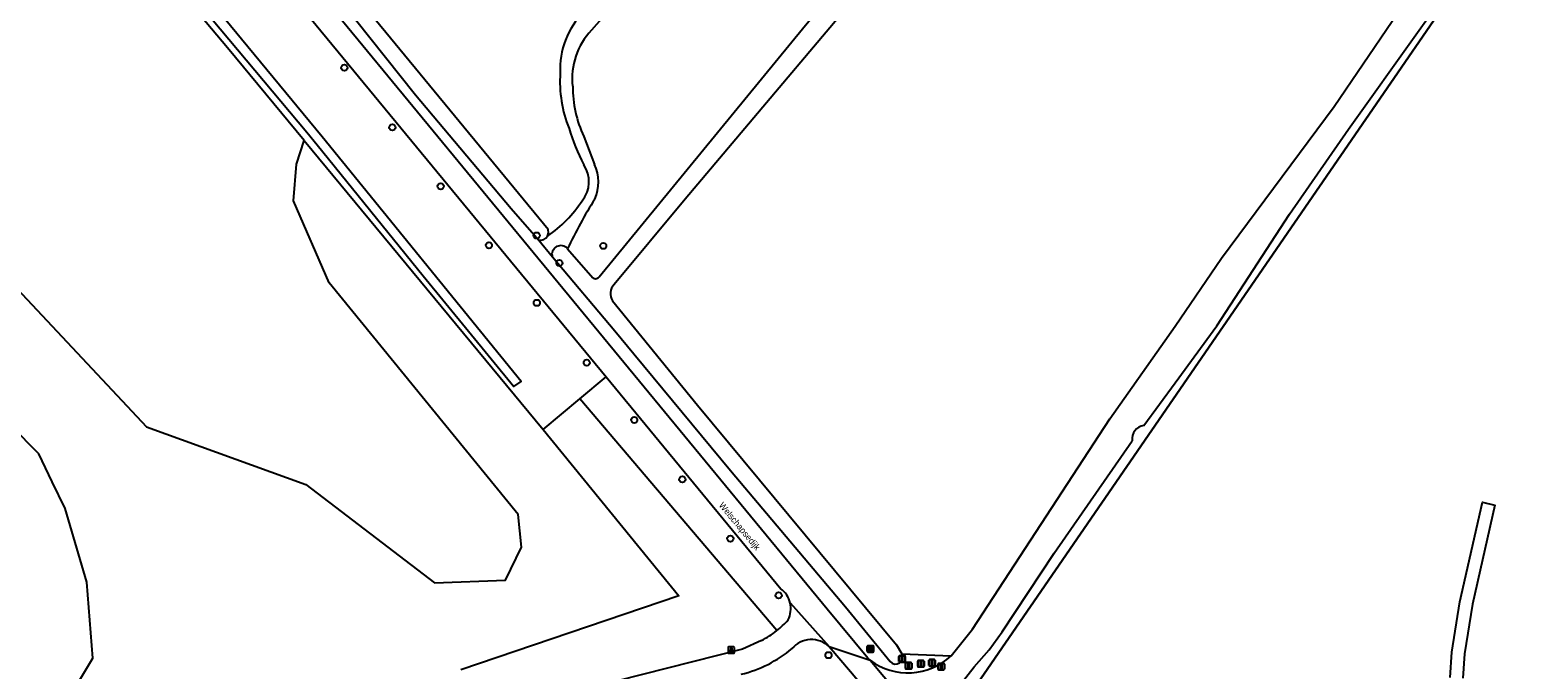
# Model space of a CAD drawing. Extents: x 156061 to 157804, y 383451 to 385640.
# Drawn here: x 156819.9 to 157057.1, y 384634.6 to 384735.1 of the extents above; entities that cross this region are included whole.
import ezdxf

# ---------------------------------------------------------------- set-up
doc = ezdxf.new("R2010")
doc.units = 0
for name, color, linetype in [('IMGEO_Afsluitpaal', 7, 'Continuous'), ('IMGEO_Berm_groen', 7, 'Continuous'), ('IMGEO_Boom', 7, 'Continuous'), ('IMGEO_Fietspad_gesloten', 7, 'Continuous'), ('IMGEO_Gemengd_bos', 7, 'Continuous'), ('IMGEO_Grasland_overig', 7, 'Continuous'), ('IMGEO_Groenvoorziening', 7, 'Continuous'), ('IMGEO_Hek', 7, 'Continuous'), ('IMGEO_Lichtpunt', 7, 'Continuous'), ('IMGEO_Loofbos', 7, 'Continuous'), ('IMGEO_Openbare_ruimte_label', 7, 'Continuous'), ('IMGEO_Waterloop', 7, 'Continuous'), ('IMGEO_Wegwijzer', 7, 'Continuous')]:
    doc.layers.add(name, color=color, linetype=linetype)

msp = doc.modelspace()

# ---------------------------------------------------------------- linework, layer by layer
at = {"layer": 'IMGEO_Afsluitpaal'}
for p, q in [((156956.65, 384636.8), (156957.44, 384636.8)), ((156957.44, 384636.8), (156956.65, 384636.8)), ((156956.55, 384635.9), (156956.55, 384636.7)), ((156956.55, 384636.7), (156956.55, 384635.9)), ((156957.44, 384635.8), (156956.65, 384635.8)), ((156956.65, 384635.8), (156957.44, 384635.8)), ((156957.54, 384636.7), (156957.54, 384635.9)), ((156957.54, 384635.9), (156957.54, 384636.7)), ((156957.57, 384634.84), (156957.57, 384635.64)), ((156957.57, 384635.64), (156957.57, 384634.84)), ((156957.67, 384635.74), (156958.46, 384635.74)), ((156958.46, 384635.74), (156957.67, 384635.74)), ((156958.46, 384634.74), (156957.67, 384634.74)), ((156957.67, 384634.74), (156958.46, 384634.74)), ((156958.56, 384635.64), (156958.56, 384634.84)), ((156958.56, 384634.84), (156958.56, 384635.64)), ((156959.52, 384635.15), (156959.52, 384635.95)), ((156959.52, 384635.95), (156959.52, 384635.15)), ((156959.62, 384636.05), (156960.41, 384636.05)), ((156960.41, 384636.05), (156959.62, 384636.05)), ((156960.41, 384635.05), (156959.62, 384635.05)), ((156959.62, 384635.05), (156960.41, 384635.05)), ((156960.51, 384635.95), (156960.51, 384635.15)), ((156960.51, 384635.15), (156960.51, 384635.95)), ((156961.26, 384635.29), (156961.26, 384636.09)), ((156961.26, 384636.09), (156961.26, 384635.29)), ((156961.36, 384636.19), (156962.15, 384636.19)), ((156962.15, 384636.19), (156961.36, 384636.19)), ((156962.15, 384635.19), (156961.36, 384635.19)), ((156961.36, 384635.19), (156962.15, 384635.19)), ((156962.25, 384636.09), (156962.25, 384635.29)), ((156962.25, 384635.29), (156962.25, 384636.09)), ((156962.72, 384634.71), (156962.72, 384635.5)), ((156962.72, 384635.5), (156962.72, 384634.71)), ((156962.82, 384635.6), (156963.61, 384635.6)), ((156963.61, 384635.6), (156962.82, 384635.6)), ((156963.61, 384634.61), (156962.82, 384634.61)), ((156962.82, 384634.61), (156963.61, 384634.61)), ((156963.71, 384635.5), (156963.71, 384634.71)), ((156963.71, 384634.71), (156963.71, 384635.5))]:
    msp.add_line(p, q, dxfattribs=at)
for points in [[(156956.97, 384636.67), (156957.12, 384636.67), (156957.12, 384635.92), (156956.97, 384635.92), (156956.97, 384636.67)], [(156957.99, 384635.62), (156958.14, 384635.62), (156958.14, 384634.87), (156957.99, 384634.87), (156957.99, 384635.62)], [(156959.94, 384635.92), (156960.09, 384635.92), (156960.09, 384635.17), (156959.94, 384635.17), (156959.94, 384635.92)], [(156961.68, 384636.07), (156961.83, 384636.07), (156961.83, 384635.32), (156961.68, 384635.32), (156961.68, 384636.07)], [(156963.14, 384635.48), (156963.29, 384635.48), (156963.29, 384634.73), (156963.14, 384634.73), (156963.14, 384635.48)]]:
    msp.add_lwpolyline(points, dxfattribs=at)
for centre, start, end in [((156956.65, 384636.7), 90, 180), ((156956.65, 384636.7), 90, 180), ((156957.44, 384636.7), 0, 90), ((156957.44, 384636.7), 360, 90), ((156956.65, 384635.9), 180, 270), ((156956.65, 384635.9), 180, 270), ((156957.44, 384635.9), 270, 0), ((156957.44, 384635.9), 270, 0), ((156957.67, 384635.64), 90, 180), ((156957.67, 384635.64), 90, 180), ((156957.67, 384634.84), 180, 270), ((156957.67, 384634.84), 180, 270), ((156958.46, 384635.64), 0, 90), ((156958.46, 384635.64), 360, 90), ((156958.46, 384634.84), 270, 0), ((156958.46, 384634.84), 270, 0), ((156959.62, 384635.95), 90, 180), ((156959.62, 384635.95), 90, 180), ((156959.62, 384635.15), 180, 270), ((156959.62, 384635.15), 180, 270), ((156960.41, 384635.95), 0, 90), ((156960.41, 384635.95), 360, 90), ((156960.41, 384635.15), 270, 0), ((156960.41, 384635.15), 270, 0), ((156961.36, 384636.09), 90, 180), ((156961.36, 384636.09), 90, 180), ((156961.36, 384635.29), 180, 270), ((156961.36, 384635.29), 180, 270), ((156962.15, 384636.09), 0, 90), ((156962.15, 384636.09), 360, 90), ((156962.15, 384635.29), 270, 0), ((156962.15, 384635.29), 270, 0), ((156962.82, 384635.5), 90, 180), ((156962.82, 384635.5), 90, 180), ((156962.82, 384634.71), 180, 270), ((156962.82, 384634.71), 180, 270), ((156963.61, 384635.5), 0, 90), ((156963.61, 384635.5), 360, 90), ((156963.61, 384634.71), 270, 0), ((156963.61, 384634.71), 270, 0)]:
    msp.add_arc(centre, 0.1, start, end, dxfattribs=at)
at = {"layer": 'IMGEO_Berm_groen'}
for points in [[(156899.9, 384702.15), (156902.04, 384699.49)], [(156906.38, 384677.17), (156910.52, 384680.62)], [(156937.33, 384640.75), (156906.38, 384677.17)], [(156956.99, 384637.11), (156964.76, 384636.78)]]:
    msp.add_lwpolyline(points, dxfattribs=at)
msp.add_arc((156957.98, 384644.09), 9.97, 233.2442, 312.8511, dxfattribs=at)
at = {"layer": 'IMGEO_Boom'}
for centre in [(156869.33, 384729.23), (156876.89, 384719.86), (156884.49, 384710.59), (156899.59, 384702.86), (156892.06, 384701.33), (156910.04, 384701.23), (156903.16, 384698.52), (156899.6, 384692.28), (156907.46, 384682.86), (156914.92, 384673.86), (156922.49, 384664.52), (156930.05, 384655.21), (156937.63, 384646.3), (156945.48, 384636.9)]:
    msp.add_circle(centre, 0.489, dxfattribs=at)
at = {"layer": 'IMGEO_Fietspad_gesloten'}
for points in [[(156952.01, 384636.1), (156951.65, 384636.45), (156945.25, 384644.12), (156913.26, 384682.92), (156857.95, 384750), (156766.23, 384861.24), (156717.24, 384920.7), (156651.9, 385000), (156634.53, 385021.05), (156628.66, 385028.19), (156628.31, 385028.6), (156616.13, 385043.37), (156611.41, 385049.1), (156600.26, 385062.64)], [(156605.09, 385050.03), (156608.82, 385046.51), (156609.37, 385045.98), (156609.93, 385045.44), (156647.34, 385000), (156714.45, 384918.5), (156763.61, 384858.81), (156853.32, 384750), (156910.52, 384680.62)], [(156910.52, 384680.62), (156937.97, 384647.33)], [(156939.44, 384645.1), (156945.58, 384638.24)], [(156934.94, 384639.2), (156931.97, 384637.82), (156888.89, 384626.92)], [(156945.58, 384638.24), (156952.01, 384636.1)], [(156945.58, 384638.24), (156948.92, 384634.34), (156956.8, 384625), (156966.54, 384613.57), (156977.24, 384601.18), (156992.9, 384582.99), (157000, 384574.89), (157056.89, 384509.94)], [(156952.01, 384636.1), (156960.39, 384626.17), (156971.95, 384612.68), (156983.28, 384599.59)]]:
    msp.add_lwpolyline(points, dxfattribs=at)
for centre, radius, start, end in [((156935.65, 384644.19), 3.9, 13.3731, 53.5565), ((156935.66, 384644.2), 3.89, 333.0449, 13.3681), ((156928.05, 384652.4), 14.9, 308.5495, 318.0269), ((156928.18, 384652.24), 14.69, 297.4079, 308.5455), ((156942.8, 384635.34), 4.01, 46.2254, 139.9072), ((156927.2, 384652.9), 19.53, 283.3871, 309.9373)]:
    msp.add_arc(centre, radius, start, end, dxfattribs=at)
at = {"layer": 'IMGEO_Gemengd_bos'}
for points in [[(156912.63, 384740.14), (156908.19, 384735.13)], [(156812.3, 384700.37), (156835.91, 384675.25), (156838.21, 384672.8), (156863.25, 384663.73), (156883.49, 384648.27), (156894.67, 384648.67), (156897.2, 384653.87), (156896.68, 384658.99), (156866.93, 384695.43), (156861.35, 384708.33), (156861.8, 384714.05), (156863, 384717.8)], [(156863, 384717.8), (156900.59, 384672.36)], [(156906.98, 384718.4), (156908.69, 384714.03)], [(156821.01, 384621.8), (156829.78, 384636.4), (156828.83, 384648.36), (156825.41, 384659.94), (156823.39, 384664.13), (156821.27, 384668.56), (156808.2, 384681.7)]]:
    msp.add_lwpolyline(points, dxfattribs=at)
for centre, radius, start, end in [((156916.17, 384727.55), 11.01, 136.4739, 186.3634), ((156923.86, 384726.27), 18.62, 179.8157, 205.0017), ((156902.85, 384711.28), 6.45, 335.3938, 25.1966), ((156970.38, 384669.75), 72.88, 147.7934, 154.8019)]:
    msp.add_arc(centre, radius, start, end, dxfattribs=at)
at = {"layer": 'IMGEO_Grasland_overig'}
for points in [[(156995.06, 384673.02), (157000, 384679.72), (157006.58, 384688.65), (157018, 384706.19), (157027.27, 384719.55), (157049, 384750), (157049.73, 384751.02), (157051.71, 384756.32), (157067.45, 384779.73), (157078.82, 384797.04), (157111.19, 384845.3), (157125.06, 384865.65), (157130.13, 384872.27), (157130.21, 384872.37), (157130.3, 384872.46), (157130.39, 384872.55)], [(156964.76, 384636.78), (156968.13, 384640.98), (156989.71, 384674.03), (157000, 384688.61), (157007.27, 384699.31), (157025, 384723.12), (157043.24, 384750), (157047.44, 384756.19)], [(156964.63, 384630.23), (156968.41, 384635.04), (156970.77, 384637.72), (156972.78, 384640.58), (156980.96, 384652.91), (156993.25, 384670.61)], [(157043.26, 384633.37), (157043.53, 384637.35), (157044.79, 384645.29), (157048.34, 384660.93), (157050.29, 384660.49), (157046.76, 384644.91), (157045.52, 384637.12), (157045.25, 384633.28)]]:
    msp.add_lwpolyline(points, dxfattribs=at)
msp.add_arc((156995.39, 384670.88), 2.16, 98.7591, 187.3492, dxfattribs=at)
at = {"layer": 'IMGEO_Groenvoorziening'}
for points in [[(156863, 384717.8), (156850.94, 384732.38), (156844.21, 384740.36), (156836.09, 384750), (156826.08, 384762.21), (156800.19, 384793.8), (156738.88, 384868.16), (156719.79, 384891.58), (156704.18, 384910.35)], [(157158.87, 384852.91), (157148.97, 384858.97), (157139.5, 384863.28), (157133.04, 384863.79), (157129.5, 384863.26), (157126.71, 384861.14), (157124.21, 384858.2), (157109.09, 384836.1), (156966.05, 384628.27), (156979.27, 384612.75)]]:
    msp.add_lwpolyline(points, dxfattribs=at)
at = {"layer": 'IMGEO_Hek'}
msp.add_lwpolyline([(156979.27, 384612.75), (156966.05, 384628.27), (157109.09, 384836.1)], dxfattribs=at)
at = {"layer": 'IMGEO_Lichtpunt'}
for p, q in [((156929.69, 384638.1), (156929.69, 384637.29)), ((156929.69, 384638.1), (156929.69, 384637.29)), ((156930.59, 384638.2), (156929.78, 384638.2)), ((156930.59, 384638.2), (156929.78, 384638.2)), ((156929.78, 384637.2), (156930.59, 384637.2)), ((156929.78, 384637.2), (156930.59, 384637.2)), ((156930.68, 384637.29), (156930.68, 384638.1)), ((156930.68, 384637.29), (156930.68, 384638.1))]:
    msp.add_line(p, q, dxfattribs=at)
for points in [[(156930.06, 384637.76), (156930.1, 384637.74), (156929.91, 384637.47), (156929.87, 384637.5), (156930.06, 384637.76)], [(156930.16, 384637.72), (156930.21, 384637.72), (156930.21, 384637.39), (156930.16, 384637.39), (156930.16, 384637.72)], [(156930.27, 384637.74), (156930.31, 384637.76), (156930.5, 384637.5), (156930.46, 384637.47), (156930.27, 384637.74)]]:
    msp.add_lwpolyline(points, dxfattribs=at)
msp.add_circle((156930.19, 384637.9), 0.0994, dxfattribs=at)
for centre, start, end in [((156929.78, 384638.1), 90, 180), ((156929.78, 384638.1), 90, 180), ((156929.78, 384637.29), 180, 270), ((156929.78, 384637.29), 180, 270), ((156930.59, 384638.1), 0, 90), ((156930.59, 384638.1), 0, 90), ((156930.59, 384637.29), 270, 0), ((156930.59, 384637.29), 270, 360)]:
    msp.add_arc(centre, 0.0946, start, end, dxfattribs=at)
at = {"layer": 'IMGEO_Loofbos'}
for points in [[(156900.59, 384672.36), (156906.38, 384677.17)], [(156900.59, 384672.36), (156921.96, 384646.24), (156887.64, 384634.58)]]:
    msp.add_lwpolyline(points, dxfattribs=at)
for centre, radius, start, end in [((156916.16, 384728.98), 12.89, 135.5682, 182.6039), ((156923.09, 384727.06), 19.85, 176.1201, 201.885), ((156939.03, 384730.36), 35.99, 197.295, 207.0582), ((156903.1, 384711.32), 4.71, 320.4606, 34.4427), ((156889.74, 384719.54), 20.36, 304.5519, 326.5832)]:
    msp.add_arc(centre, radius, start, end, dxfattribs=at)
at = {"layer": 'IMGEO_Waterloop'}
for points in [[(156901.29, 384702.77), (156901.45, 384703.28), (156901.39, 384703.81), (156863.3, 384750), (156839.16, 384779.55), (156830.46, 384789.83)], [(156828.52, 384788.04), (156840.15, 384774.25), (156860.19, 384750), (156871.1, 384736.8), (156880.52, 384724.99), (156895.57, 384707.11), (156899.9, 384702.15)], [(156909.41, 384696.38), (156941.87, 384735.94), (156953.6, 384750), (156967.04, 384766.13), (156980.7, 384781.58)], [(156982.6, 384779.99), (156976.6, 384772.41), (156957.89, 384750), (156922.91, 384708.59), (156911.79, 384695.16)], [(156837.41, 384750.16), (156837.54, 384750), (156863.41, 384719.1), (156865.07, 384717.11), (156881.71, 384696.52), (156896, 384679.11), (156897.15, 384679.89), (156865.85, 384718.39), (156839.75, 384750), (156838.72, 384751.26), (156838.16, 384750.79), (156837.41, 384750.16)], [(156904.43, 384700.78), (156908.42, 384696.19)], [(156902.04, 384699.49), (156911.88, 384687.9), (156914.88, 384684.27), (156930.08, 384665.91), (156948.15, 384644.48), (156955.17, 384635.88)], [(156911.52, 384692.57), (156924.85, 384676.2), (156956.19, 384638.52), (156956.99, 384637.11)]]:
    msp.add_lwpolyline(points, dxfattribs=at)
for centre, radius, start, end in [((156900.17, 384703.41), 1.29, 257.867, 330.2723), ((156903.37, 384699.88), 1.39, 40.2824, 196.1053), ((156908.82, 384696.78), 0.709, 235.7789, 326.0137), ((156913.17, 384693.71), 2.01, 133.6096, 214.5842), ((156956.01, 384636.6), 1.11, 220.6341, 27.2814)]:
    msp.add_arc(centre, radius, start, end, dxfattribs=at)
at = {"layer": 'IMGEO_Wegwijzer'}
for p, q in [((156951.58, 384637.48), (156951.58, 384638.28)), ((156951.58, 384638.28), (156951.58, 384637.48)), ((156951.68, 384638.38), (156952.47, 384638.38)), ((156952.47, 384638.38), (156951.68, 384638.38)), ((156952.47, 384637.38), (156951.68, 384637.38)), ((156951.68, 384637.38), (156952.47, 384637.38)), ((156952.57, 384638.28), (156952.57, 384637.48)), ((156952.57, 384637.48), (156952.57, 384638.28))]:
    msp.add_line(p, q, dxfattribs=at)
for points in [[(156951.68, 384638.12), (156952.47, 384638.12), (156952.47, 384637.65), (156951.68, 384637.65), (156951.68, 384638.12)], [(156951.75, 384637.97), (156951.75, 384637.88), (156951.75, 384637.8), (156952.16, 384637.8), (156952.16, 384637.72), (156952.4, 384637.88), (156952.16, 384638.05), (156952.16, 384637.97), (156951.75, 384637.97)]]:
    msp.add_lwpolyline(points, dxfattribs=at)
for centre, start, end in [((156951.68, 384638.28), 90, 180), ((156951.68, 384638.28), 90, 180), ((156951.68, 384637.48), 180, 270), ((156951.68, 384637.48), 180, 270), ((156952.47, 384638.28), 0, 90), ((156952.47, 384638.28), 360, 90), ((156952.47, 384637.48), 270, 0), ((156952.47, 384637.48), 270, 0)]:
    msp.add_arc(centre, 0.1, start, end, dxfattribs=at)

# ---------------------------------------------------------------- texts
at = {"layer": 'IMGEO_Openbare_ruimte_label'}
msp.add_text('Welschapsedijk', height=1, rotation=309.5635, dxfattribs=at).set_placement((156928.16, 384660.43))

doc.saveas('drawing.dxf')
